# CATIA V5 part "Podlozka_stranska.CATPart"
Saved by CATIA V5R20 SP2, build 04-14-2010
Part number: Part1.1
Bounding box of the stored display mesh (mm): x -4.999 to 4.999, y -4.999 to 4.999, z 0 to 3
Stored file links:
  C:\Documents and Settings\Administrator\My Documents\Hobi_dokumenti\CAD_CNC\Clap_CATIA\Podlozka_stranska.CATPart
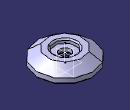
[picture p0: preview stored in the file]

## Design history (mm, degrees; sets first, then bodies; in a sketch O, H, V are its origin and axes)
StDynAnalysisRootNodeFeature1 "CATStDynAnalysisRootNodeName"
Set1
  Line1: type PtDir, RefPoint Sketch1.O, Direction Sketch1.V, Start 0, End 3
Body1 (main body)
  Sketch1 on yz-plane, origin (0, 0, 0), H (0, 1, 0), V (0, 0, 1)
    point P1 (-2, 0)
    line L1 (-2, 0) -> (-5, 0)
    line L2 (-5, 0) -> (-5, 1)
    line L3 (-2, 1) -> (-2, 0)
    point P3 (-5, 1)
    point P4 (-2, 1)
    line L4 (-2, 1) -> (-1, 1)
    point P5 (-1, 1)
    line L5 (-1, 1) -> (-1, 1.6)
    point P6 (-1, 1.6)
    line L6 (-1, 1.6) -> (-2, 1.6)
    point P7 (-2, 1.6)
    line L7 (-2, 1.6) -> (-2, 2.3)
    point P8 (-2, 2.3)
    line L8 (-2, 2.3) -> (-3.2, 2.3)
    point P9 (-3.2, 2.3)
    line L9 (-5, 1) -> (-3.2, 2.3)
    reference intersected line E1 through (0, 0) direction (-1, 0) from xy-plane
    reference intersected line E3 through (0, 0) direction (0, 1) from zx-plane
    distance V L2 = 5
    distance V L3 = 2
    distance P8 P9 = 1.2
    distance P5 P6 = 0.6
    distance P7 P8 = 0.7
    distance P6 P7 = 1
    distance P4 P1 = 1
    distance V L5 = 1
    coincidence: P1 H, P3 L4
    horizontal: L1 H, L4 H, L6 H, L8 H, E1 H
    vertical: L2 V, L3 V, L5 V, L7 V, E3 V
    perpendicularity: E1 L5
  Shaft1: profile Sketch1, axis Line1, angle 360
  Chamfer1: length 0.2, angle 45, on edge [face of Shaft1 from Sketch1.L1 | face of Shaft1 from Sketch1.L2]; edge [face of Shaft1 from Sketch1.L3 | face of Shaft1 from Sketch1.L1]; edge [face of Shaft1 from Sketch1.L8 | face of Shaft1 from Sketch1.L7]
